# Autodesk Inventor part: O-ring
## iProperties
Shininess: 64.0
Length Units: 11272
Angle Units: 11279
Time Units: 11290
Mass Units: 11286
Length Display Precision: 3
Angle Display Precision: 2
Compacted: True
Part Number: O-ring
Document SubType Name: Modeling
Created: 2003-08
Designer: jpittman
Manufacturer: Standard
Standards Organization: Custom
Density: 0.0
Volumn: 0.0
Area: 0.0
PropertySet Name: Model Information
Control State: 0
Master: False
Checked Out: False
Author: jpittman
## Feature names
1. Revolution1
